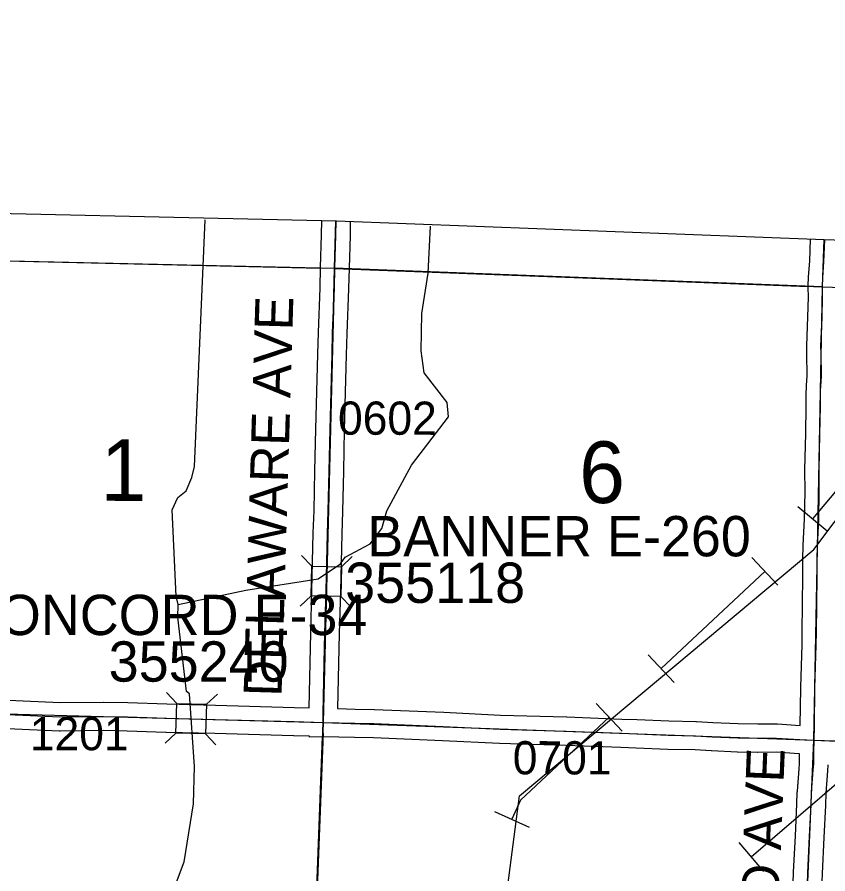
# Model space of a CAD drawing. Extents: x -157.2 to -99.3, y 12.2 to 46.2.
# Drawn here: x -139.086 to -137.377, y 39.661 to 41.468 of the extents above; entities that cross this region are included whole.
import ezdxf

# ---------------------------------------------------------------- set-up
doc = ezdxf.new("R2010")
doc.units = 0
for name, color, linetype in [('tdCoClipBndry', 7, 'Continuous'), ('tdCoCoBndry', 7, 'Continuous'), ('tdCoCoBndryPart', 7, 'Continuous'), ('tdCoHydroRiver', 7, 'Continuous'), ('tdCoPipe', 7, 'Continuous'), ('tdCoPipe1', 7, 'Continuous'), ('tdCoPipe2', 7, 'Continuous'), ('tdCoSecRdNmbr', 7, 'Continuous'), ('tdCoSecRdTxt', 7, 'Continuous'), ('tdCoSecRteBand', 7, 'Continuous'), ('tdCoSecRteCL', 7, 'Continuous'), ('tdCoSectLine', 7, 'Continuous'), ('tdCoSectLinePart', 7, 'Continuous'), ('tdCoSectNmbr', 7, 'Continuous'), ('tdCoStrucSec', 7, 'Continuous'), ('tdCoStrucSecCoName', 7, 'Continuous'), ('tdCoStrucSecFHWANum', 7, 'Continuous'), ('tdCoSurfAsphalt', 7, 'Continuous'), ('tdCoSurfGravel', 7, 'Continuous'), ('tdCoTwpBndry', 7, 'Continuous'), ('tdCoTwpBndryShd', 7, 'Continuous')]:
    doc.layers.add(name, color=color, linetype=linetype)

msp = doc.modelspace()

# ---------------------------------------------------------------- linework, layer by layer
at = {"layer": 'tdCoClipBndry'}
msp.add_lwpolyline([(-150.407, 41.4676), (-149.3946, 41.4438), (-148.3968, 41.411), (-147.4001, 41.3615), (-145.4135, 41.2969), (-142.396, 41.1563), (-141.4008, 41.1294), (-139.4104, 41.0607), (-138.4128, 41.0377), (-137.3849, 40.9986), (-130.3617, 40.7621)], dxfattribs=at)
at = {"layer": 'tdCoCoBndry'}
for points in [[(-152.9518, 41.3883), (-152.409, 41.3796), (-151.4143, 41.374), (-150.4076, 41.3676), (-149.397, 41.3439), (-148.4001, 41.3111), (-147.4042, 41.2616), (-146.4159, 41.2271), (-145.4182, 41.197), (-144.4306, 41.151), (-143.3778, 41.1032), (-142.3996, 41.0564), (-141.4043, 41.0295), (-140.4086, 40.9954), (-139.4133, 40.9608), (-138.4166, 40.9378), (-137.3885, 40.8986), (-136.3904, 40.8656), (-135.3934, 40.8324), (-134.3958, 40.7988)], [(-138.4166, 40.9378), (-138.4171, 40.9377), (-137.3885, 40.8986)], [(-137.3885, 40.8986), (-138.4166, 40.9378)]]:
    msp.add_lwpolyline(points, dxfattribs=at)
at = {"layer": 'tdCoCoBndryPart'}
for points in [[(-139.3836, 40.9601), (-138.4465, 40.9385)], [(-137.4185, 40.8998), (-138.3866, 40.9367)], [(-138.3866, 40.9366), (-137.4185, 40.8998)]]:
    msp.add_lwpolyline(points, dxfattribs=at)
at = {"layer": 'tdCoHydroRiver'}
for points in [[(-138.7466, 40.2291), (-138.7508, 40.2466), (-138.7593, 40.4283), (-138.7474, 40.4548), (-138.7296, 40.4684), (-138.7176, 40.4964), (-138.7122, 40.5199), (-138.6896, 41.0398)], [(-138.7466, 40.2291), (-138.6036, 40.2593), (-138.4513, 40.283), (-138.4045, 40.3146), (-138.3946, 40.3285), (-138.3416, 40.3568), (-138.3169, 40.3892), (-138.3063, 40.4267), (-138.2543, 40.5229), (-138.1768, 40.6246), (-138.1791, 40.6547), (-138.2276, 40.7177), (-138.234, 40.7637), (-138.2331, 40.8425), (-138.2194, 40.9273), (-138.2149, 41.0264)], [(-138.7942, 39.5254), (-138.7339, 39.686), (-138.7142, 39.8084), (-138.7117, 39.8872), (-138.7226, 40.0406), (-138.7288, 40.0455), (-138.7475, 40.2023), (-138.7466, 40.2291)]]:
    msp.add_lwpolyline(points, dxfattribs=at)
at = {"layer": 'tdCoPipe'}
msp.add_lwpolyline([(-145.5545, 32.0407), (-145.4652, 31.9559), (-145.2641, 32.039), (-144.2371, 32.0131), (-143.232, 33.3859), (-142.9301, 33.9124), (-142.0867, 34.756), (-141.6374, 35.6825), (-141.5355, 35.8566), (-140.3685, 37.1582), (-139.4239, 38.0364), (-138.0693, 39.5013), (-138.0266, 39.825), (-137.4064, 40.3449), (-136.8596, 41.0707)], dxfattribs=at)
at = {"layer": 'tdCoPipe1'}
for p, q in [((-137.44, 40.4356), (-137.3787, 40.384)), ((-137.5369, 40.3278), (-137.4821, 40.2693)), ((-137.7559, 40.1227), (-137.7011, 40.0642)), ((-137.8654, 40.0202), (-137.8106, 39.9617)), ((-138.0796, 39.7924), (-138.0065, 39.7594))]:
    msp.add_line(p, q, dxfattribs=at)
for points in [[(-137.2162, 40.6394), (-137.4093, 40.4098)], [(-137.5095, 40.2985), (-137.7285, 40.0935)], [(-137.838, 39.9909), (-138.025, 39.8159), (-138.043, 39.7759)]]:
    msp.add_lwpolyline(points, dxfattribs=at)
at = {"layer": 'tdCoPipe2'}
msp.add_line((-137.5647, 39.7265), (-137.5125, 39.6656), dxfattribs=at)
msp.add_lwpolyline([(-137.3236, 39.9009), (-137.3389, 39.8672), (-137.5386, 39.6961)], dxfattribs=at)
at = {"layer": 'tdCoSecRteBand'}
for points in [[(-138.4706, 40.0108), (-138.4684, 40.1055), (-138.4671, 40.1691), (-138.4671, 40.1693), (-138.4671, 40.1694), (-138.4644, 40.2583), (-138.4617, 40.3793), (-138.4617, 40.3795), (-138.4617, 40.3797), (-138.46, 40.4266), (-138.4583, 40.5109), (-138.4583, 40.511), (-138.4583, 40.511), (-138.4563, 40.5983), (-138.4563, 40.5984), (-138.4563, 40.5984), (-138.4521, 40.7568), (-138.4521, 40.7568), (-138.4521, 40.7568), (-138.4509, 40.8024), (-138.4509, 40.8026), (-138.4509, 40.8028), (-138.4472, 40.897), (-138.4462, 40.9396), (-138.4462, 40.9397), (-138.4462, 40.9398), (-138.4442, 41.0085), (-138.4436, 41.0384)], [(-138.3836, 41.0366), (-138.3842, 41.0071), (-138.3842, 41.007), (-138.3842, 41.0069), (-138.3862, 40.9382), (-138.3872, 40.8953), (-138.3872, 40.8951), (-138.3872, 40.8949), (-138.3909, 40.8006), (-138.3921, 40.7552), (-138.3963, 40.5969), (-138.3983, 40.5097), (-138.4, 40.4251), (-138.4, 40.4249), (-138.4, 40.4246), (-138.4017, 40.3778), (-138.4044, 40.2569), (-138.4044, 40.2568), (-138.4044, 40.2566), (-138.4071, 40.1678), (-138.4084, 40.1043), (-138.4084, 40.1043), (-138.4084, 40.1042), (-138.4106, 40.0092), (-138.4096, 40.0092), (-138.3736, 40.0082), (-138.3334, 40.0077), (-138.3329, 40.0077), (-138.3325, 40.0077), (-138.1867, 40.0015), (-138.1866, 40.0015), (-138.1865, 40.0015), (-138.0667, 39.9956), (-137.9277, 39.9917), (-137.9276, 39.9917), (-137.9274, 39.9917), (-137.811, 39.9872), (-137.7787, 39.986), (-137.7787, 39.986), (-137.7786, 39.986), (-137.7124, 39.9833), (-137.6549, 39.9821), (-137.6543, 39.9821), (-137.6537, 39.982), (-137.6195, 39.9798), (-137.5657, 39.9776), (-137.5247, 39.9769), (-137.4851, 39.9771), (-137.484, 39.9772), (-137.483, 39.9771), (-137.4351, 39.9739)], [(-137.4351, 39.9739), (-137.4341, 40.053), (-137.4341, 40.0533), (-137.4341, 40.0535), (-137.4314, 40.1443), (-137.4309, 40.1707), (-137.4297, 40.2884), (-137.4294, 40.3236), (-137.4294, 40.3239), (-137.4294, 40.3242), (-137.4287, 40.3533), (-137.4287, 40.3535), (-137.4287, 40.3538), (-137.4262, 40.409), (-137.425, 40.4662), (-137.4252, 40.5126), (-137.4252, 40.5131), (-137.4252, 40.5135), (-137.4235, 40.5889), (-137.4225, 40.6471), (-137.4223, 40.6795), (-137.4223, 40.6804), (-137.4222, 40.6813), (-137.4216, 40.6911), (-137.4206, 40.7107), (-137.4211, 40.7583), (-137.4214, 40.773), (-137.4214, 40.7738), (-137.4213, 40.7746), (-137.4191, 40.8354), (-137.4179, 40.8771), (-137.4181, 40.898), (-137.4181, 40.9009), (-137.4182, 40.9015), (-137.4181, 40.9021), (-137.4176, 40.9184), (-137.4176, 40.919), (-137.4176, 40.9197), (-137.4152, 40.9529), (-137.4135, 40.9996)], [(-139.104, 40.0267), (-138.9951, 40.0218), (-138.9037, 40.0228), (-138.9033, 40.0228), (-138.903, 40.0228), (-138.8529, 40.022), (-138.8526, 40.022), (-138.8523, 40.022), (-138.7703, 40.0191), (-138.6679, 40.0166), (-138.6678, 40.0166), (-138.6677, 40.0166), (-138.5013, 40.0117), (-138.4706, 40.0108)], [(-137.4514, 39.5964), (-137.4491, 39.664), (-137.4491, 39.6642), (-137.4491, 39.6644), (-137.4454, 39.7406), (-137.4454, 39.7407), (-137.4454, 39.7407), (-137.442, 39.8077), (-137.4413, 39.8335), (-137.4412, 39.8342), (-137.4412, 39.835), (-137.4375, 39.8821), (-137.4368, 39.8935), (-137.4368, 39.9137), (-137.437, 39.9137), (-137.437, 39.914), (-137.4372, 39.914), (-137.4373, 39.914), (-137.4377, 39.914), (-137.4381, 39.914), (-137.4858, 39.9171), (-137.5247, 39.9169), (-137.525, 39.9169), (-137.5254, 39.9169), (-137.5671, 39.9176), (-137.5674, 39.9177), (-137.5678, 39.9177), (-137.6223, 39.9199), (-137.6226, 39.9199), (-137.623, 39.9199), (-137.6569, 39.9221), (-137.7139, 39.9233), (-137.7142, 39.9233), (-137.7145, 39.9233), (-137.781, 39.9261), (-137.8133, 39.9273), (-137.9296, 39.9317), (-138.0688, 39.9357), (-138.0691, 39.9357), (-138.0694, 39.9357), (-138.1894, 39.9416), (-138.3346, 39.9477), (-138.3746, 39.9482), (-138.3748, 39.9482), (-138.375, 39.9482), (-138.4405, 39.95), (-138.4697, 39.9493), (-138.4697, 39.9508), (-138.503, 39.9517), (-138.503, 39.9517), (-138.5031, 39.9517), (-138.6694, 39.9566), (-138.7719, 39.9591), (-138.7721, 39.9591), (-138.7723, 39.9591), (-138.8541, 39.962), (-138.9035, 39.9628), (-138.9953, 39.9618), (-138.9962, 39.9618), (-138.997, 39.9618), (-139.1066, 39.9667)], [(-137.3769, 39.8908), (-137.3776, 39.8782), (-137.3776, 39.878), (-137.3777, 39.8777), (-137.3813, 39.8311), (-137.382, 39.8057), (-137.382, 39.8053), (-137.3821, 39.805), (-137.3855, 39.7377), (-137.3892, 39.6618), (-137.3914, 39.5942)]]:
    msp.add_lwpolyline(points, dxfattribs=at)
at = {"layer": 'tdCoSecRteCL'}
for points in [[(-138.4404, 39.98), (-138.4408, 39.9984), (-138.4384, 40.1049), (-138.4371, 40.1685), (-138.4344, 40.2576), (-138.4317, 40.3786), (-138.43, 40.4257), (-138.4283, 40.5103), (-138.4263, 40.5976), (-138.4221, 40.756), (-138.4209, 40.8016), (-138.4172, 40.896), (-138.4162, 40.9389), (-138.4142, 41.0078), (-138.4136, 41.0378)], [(-137.4061, 39.9428), (-137.4051, 39.9732), (-137.4041, 40.0526), (-137.4014, 40.1436), (-137.4009, 40.1703), (-137.3997, 40.2881), (-137.3994, 40.3234), (-137.3987, 40.3525), (-137.3962, 40.408), (-137.395, 40.4659), (-137.3952, 40.5128), (-137.3935, 40.5883), (-137.3925, 40.6467), (-137.3923, 40.6793), (-137.3916, 40.6894), (-137.3906, 40.7101), (-137.3911, 40.7587), (-137.3914, 40.7735), (-137.3891, 40.8344), (-137.3879, 40.8768), (-137.3881, 40.8983), (-137.3882, 40.9012), (-137.3877, 40.9175), (-137.3852, 40.9513), (-137.3836, 40.9985)], [(-139.4455, 40.0075), (-139.4085, 40.0063), (-139.2489, 40.0019), (-139.1054, 39.9967), (-138.9956, 39.9918), (-138.9034, 39.9928), (-138.8533, 39.992), (-138.7712, 39.9891), (-138.6686, 39.9866), (-138.5022, 39.9817), (-138.4404, 39.98)], [(-138.4404, 39.98), (-138.3742, 39.9782), (-138.3337, 39.9777), (-138.188, 39.9716), (-138.0679, 39.9656), (-137.9286, 39.9617), (-137.8122, 39.9573), (-137.7799, 39.956), (-137.7133, 39.9533), (-137.6556, 39.9521), (-137.6211, 39.9499), (-137.5666, 39.9476), (-137.5249, 39.9469), (-137.4849, 39.9472), (-137.4361, 39.9439), (-137.4061, 39.9428)], [(-137.448, 38.9461), (-137.4458, 38.9878), (-137.4428, 39.0682), (-137.4404, 39.1101), (-137.4369, 39.2314), (-137.4349, 39.2679), (-137.433, 39.297), (-137.4295, 39.3671), (-137.4276, 39.424), (-137.4273, 39.4618), (-137.4268, 39.478), (-137.4214, 39.5952), (-137.4192, 39.663), (-137.4155, 39.7392), (-137.412, 39.8065), (-137.4113, 39.8327), (-137.4076, 39.88), (-137.4068, 39.8926), (-137.4068, 39.918), (-137.4061, 39.9428)], [(-137.4061, 39.9428), (-137.3616, 39.941), (-137.2677, 39.9358), (-137.2065, 39.9343), (-137.1426, 39.9326), (-137.0445, 39.9289), (-136.9515, 39.923), (-136.8568, 39.919), (-136.7557, 39.9156), (-136.6588, 39.9111), (-136.5577, 39.9065), (-136.4484, 39.9013), (-136.4084, 39.8998)]]:
    msp.add_lwpolyline(points, dxfattribs=at)
at = {"layer": 'tdCoSectLine'}
for points in [[(-138.4166, 40.9378), (-138.414, 41.0378)], [(-137.3885, 40.8986), (-137.3845, 40.9985)], [(-139.4133, 40.9608), (-138.4166, 40.9378)], [(-138.4408, 39.98), (-138.4166, 40.9377)], [(-138.4166, 40.9378), (-138.4171, 40.9377), (-138.4166, 40.9377)], [(-138.4166, 40.9377), (-138.4166, 40.9378)], [(-137.3885, 40.8986), (-138.4166, 40.9378)], [(-138.4166, 40.9377), (-137.3885, 40.8986)], [(-137.4064, 39.9428), (-137.3885, 40.8986)], [(-137.3885, 40.8986), (-136.3904, 40.8656)], [(-139.4459, 40.0075), (-138.4408, 39.98)], [(-138.4788, 38.9821), (-138.4408, 39.98)], [(-138.4408, 39.98), (-137.4064, 39.9428)], [(-137.4484, 38.9461), (-137.4064, 39.9428)], [(-137.4064, 39.9428), (-136.4088, 39.8998)]]:
    msp.add_lwpolyline(points, dxfattribs=at)
at = {"layer": 'tdCoSectLinePart'}
for points in [[(-139.3836, 40.9601), (-138.4465, 40.9385)], [(-137.4185, 40.8998), (-138.3866, 40.9367)], [(-138.3866, 40.9366), (-137.4185, 40.8998)], [(-138.4776, 39.0121), (-138.4419, 39.9502)]]:
    msp.add_lwpolyline(points, dxfattribs=at)
at = {"layer": 'tdCoStrucSec'}
for p, q in [((-138.4649, 40.3099), (-138.4866, 40.3325)), ((-138.4024, 40.3084), (-138.3797, 40.3301)), ((-138.4663, 40.2473), (-138.489, 40.2256)), ((-138.4038, 40.2459), (-138.3821, 40.2232)), ((-138.7493, 40.0203), (-138.7708, 40.0431)), ((-138.6867, 40.0184), (-138.6639, 40.0399)), ((-138.7511, 39.9577), (-138.7739, 39.9362)), ((-138.6886, 39.9559), (-138.6671, 39.9331))]:
    msp.add_line(p, q, dxfattribs=at)
for points in [[(-138.4663, 40.2473), (-138.4649, 40.3099), (-138.4024, 40.3084), (-138.4038, 40.2459)], [(-138.7493, 40.0203), (-138.6867, 40.0184), (-138.6886, 39.9559), (-138.7511, 39.9577)]]:
    msp.add_lwpolyline(points, close=True, dxfattribs=at)
at = {"layer": 'tdCoSurfAsphalt'}
msp.add_lwpolyline([(-139.1054, 39.9967), (-138.9956, 39.9918), (-138.9034, 39.9928), (-138.8533, 39.992), (-138.7712, 39.9891), (-138.6686, 39.9866), (-138.5022, 39.9817), (-138.4404, 39.98), (-138.3742, 39.9782), (-138.3337, 39.9777), (-138.188, 39.9716), (-138.0679, 39.9656), (-137.9286, 39.9617), (-137.8122, 39.9573), (-137.7799, 39.956), (-137.7133, 39.9533), (-137.6556, 39.9521), (-137.6211, 39.9499), (-137.5666, 39.9476), (-137.5249, 39.9469), (-137.4849, 39.9472), (-137.4361, 39.9439), (-137.4061, 39.9428), (-137.3616, 39.941)], dxfattribs=at)
at = {"layer": 'tdCoSurfGravel'}
for points in [[(-138.4162, 40.9389), (-138.4142, 41.0078), (-138.4136, 41.0378)], [(-137.3881, 40.8983), (-137.3882, 40.9012), (-137.3877, 40.9175), (-137.3852, 40.9513), (-137.3836, 40.9985)], [(-138.4404, 39.98), (-138.4408, 39.9984), (-138.4384, 40.1049), (-138.4371, 40.1685), (-138.4344, 40.2576), (-138.4317, 40.3786), (-138.43, 40.4257), (-138.4283, 40.5103), (-138.4263, 40.5976), (-138.4221, 40.756), (-138.4209, 40.8016), (-138.4172, 40.896), (-138.4162, 40.9389)], [(-137.4061, 39.9428), (-137.4051, 39.9732), (-137.4041, 40.0526), (-137.4014, 40.1436), (-137.4009, 40.1703), (-137.3997, 40.2881), (-137.3994, 40.3234), (-137.3987, 40.3525), (-137.3962, 40.408), (-137.395, 40.4659), (-137.3952, 40.5128), (-137.3935, 40.5883), (-137.3925, 40.6467), (-137.3923, 40.6793), (-137.3916, 40.6894), (-137.3906, 40.7101), (-137.3911, 40.7587), (-137.3914, 40.7735), (-137.3891, 40.8344), (-137.3879, 40.8768), (-137.3881, 40.8983)], [(-137.448, 38.9461), (-137.4458, 38.9878), (-137.4428, 39.0682), (-137.4404, 39.1101), (-137.4369, 39.2314), (-137.4349, 39.2679), (-137.433, 39.297), (-137.4295, 39.3671), (-137.4276, 39.424), (-137.4273, 39.4618), (-137.4268, 39.478), (-137.4214, 39.5952), (-137.4192, 39.663), (-137.4155, 39.7392), (-137.412, 39.8065), (-137.4113, 39.8327), (-137.4076, 39.88), (-137.4068, 39.8926), (-137.4068, 39.918), (-137.4061, 39.9428)]]:
    msp.add_lwpolyline(points, dxfattribs=at)
at = {"layer": 'tdCoTwpBndry'}
msp.add_lwpolyline([(-138.4763, 39.0106), (-138.4401, 39.9575)], dxfattribs=at)
at = {"layer": 'tdCoTwpBndryShd'}
for points in [[(-150.4076, 41.3676), (-149.397, 41.3439), (-148.4001, 41.3111), (-147.4042, 41.2616), (-146.4159, 41.2271), (-145.4182, 41.197), (-144.4306, 41.151), (-143.3778, 41.1032), (-142.3996, 41.0564), (-141.4043, 41.0295), (-140.4086, 40.9954), (-139.4133, 40.9608), (-138.4166, 40.9378), (-137.3885, 40.8986), (-136.3904, 40.8656), (-135.3934, 40.8324), (-134.3958, 40.7988)], [(-138.4166, 40.9377), (-138.4408, 39.98), (-138.4788, 38.9821), (-138.5068, 37.9865), (-138.5381, 36.9863), (-138.5686, 35.9896), (-138.5981, 34.9835)]]:
    msp.add_lwpolyline(points, dxfattribs=at)

# ---------------------------------------------------------------- texts
at = {"layer": 'tdCoSecRdNmbr'}
for s, rotation, p in [('0602', 359.8944, (-138.4096, 40.587)), ('1201', 359.8939, (-139.0592, 39.9216)), ('0701', 359.8947, (-138.0412, 39.8707))]:
    msp.add_text(s, height=0.07, rotation=rotation, dxfattribs=at).set_placement(p)
at = {"layer": 'tdCoSecRdTxt'}
for s, rotation, p in [('DELAWARE AVE', 88.2903, (-138.5287, 40.0338)), ('EASTLAND AVE', 87.7319, (-137.4995, 39.116))]:
    msp.add_text(s, height=0.08, rotation=rotation, dxfattribs=at).set_placement(p)
at = {"layer": 'tdCoSectNmbr'}
for s, rotation, p in [('1', 359.8939, (-138.9102, 40.4475)), ('6', 359.8947, (-137.9013, 40.4429))]:
    msp.add_text(s, height=0.13, rotation=rotation, dxfattribs=at).set_placement(p)
at = {"layer": 'tdCoStrucSecCoName'}
for s, p in [('BANNER E-260', (-138.3478, 40.3304)), ('CONCORD E-34', (-139.2065, 40.1643))]:
    msp.add_text(s, height=0.085, dxfattribs=at).set_placement(p)
at = {"layer": 'tdCoStrucSecFHWANum'}
for s, p in [('355118', (-138.3944, 40.2322)), ('355240', (-138.893, 40.0661))]:
    msp.add_text(s, height=0.085, dxfattribs=at).set_placement(p)

doc.saveas('drawing.dxf')
